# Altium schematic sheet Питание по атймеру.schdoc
size 148 x 115 mm
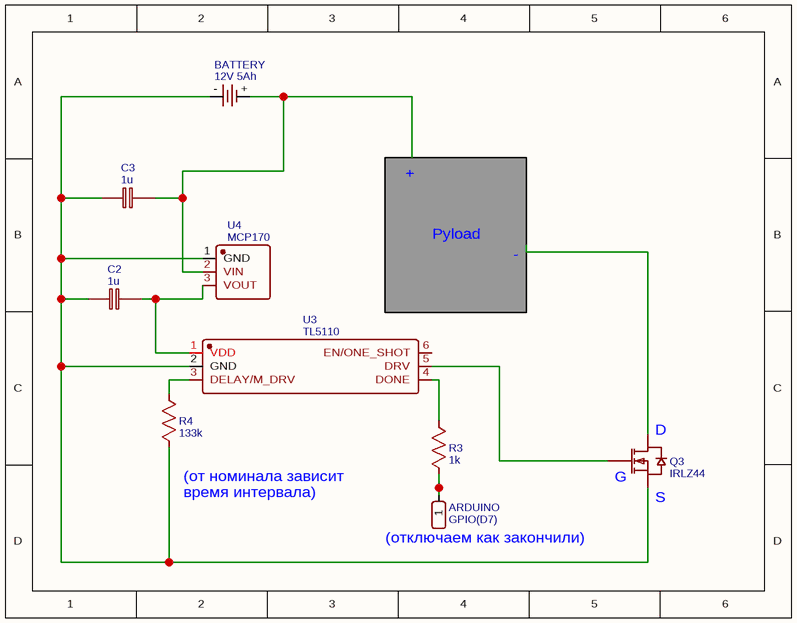
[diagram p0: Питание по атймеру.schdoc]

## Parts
ARDUINO  GPIO(D7)  [HDR-M-2.54_1X1]
BATTERY  12V 5Ah  [BATTERY-SMD-MY-2032]
C2  1u  [C0603]
C3  1u  [C0603]
Q3  IRLZ44  [TO-220-3_L10.0-W4.5-P2.54-T]
R3  1k  [R0603]
R4  133k  [R0603]
U3  TL5110  [TSOT-23-6_L2.9-W1.6-P0.95-LS2.8-BR]
U4  MCP170  [SOT-89-3_L4.5-W2.4-P1.50-LS4.0-BR]

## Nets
NetARDUINO_1: ARDUINO.1 R3.2
NetBATTERY_+: BATTERY.+(BAT-) C3.2 U4.2(VIN)
NetBATTERY_-: BATTERY.-(BAT+) C2.1 C3.1 Q3.3(S) R4.2 U3.2(GND) U4.1(GND)
NetC2_2: C2.2 U3.1(VDD) U4.3(VOUT)
NetQ3_1: Q3.1(G) U3.5(DRV)
NetR3_1: R3.1 U3.4(DONE)
NetR4_1: R4.1 U3.3(DELAY/M_DRV)

Not connected (* = marked no-connect by the designer): Q3 2(D); U3 6(EN/ONE_SHOT)

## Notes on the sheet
- +
- Pyload
- -
- (near Q3) D
- (near R4) (от номинала зависит
  время интервала)
- (near Q3) G
- (near Q3) S
- (near ARDUINO) (отключаем как закончили)

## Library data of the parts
ARDUINO = GPIO(D7): Contributor: LCEDA_Lib
BATTERY = 12V 5Ah: Manufacturer: MYOUNG(美阳); Manufacturer Part: MY-2032-10; Contributor: lcsc
C2 C3 = 1u: nameAlias: Value(F); Contributor: LCEDA_Lib
Q3 = IRLZ44: Manufacturer: Infineon(英飞凌); Manufacturer Part: IRLZ44NPBF
R3 = 1k: nameAlias: Value(Ω); Contributor: LCEDA_Lib
R4 = 133k: nameAlias: Value(Ω); Contributor: LCEDA_Lib
U3 = TL5110: Manufacturer: TI(德州仪器); Manufacturer Part: TPL5110DDCR; Contributor: lcsc; nameAlias: Value
U4 = MCP170: Manufacturer: MICROCHIP(美国微芯); Manufacturer Part: MCP1701AT-5002I/MB; Contributor: lcsc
